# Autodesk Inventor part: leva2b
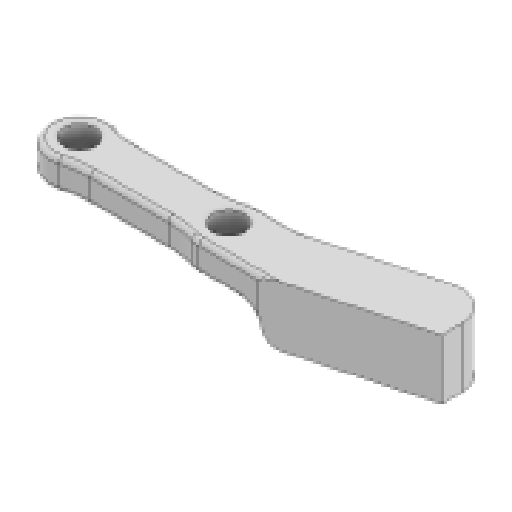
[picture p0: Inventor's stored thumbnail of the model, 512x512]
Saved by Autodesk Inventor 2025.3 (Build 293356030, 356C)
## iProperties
Created: 2026-03
Part Number: leva2b
Material: Generico
Document SubType Name: Modeling
Designer: R5800u
Density: 1 g/cm^3
Appearance: Default
Author: R5800u
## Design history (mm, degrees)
sketch "Schizzo1"
  geometry: L1 (7.5, 2.5)-(-7.5, 2.5); L2 (-7.5, 2.5)-(-7.5, -2.5); L3 (-7.5, -2.5)-(7.5, -2.5); L4 (7.5, -2.5)-(7.5, 2.5); L5 (7.5, 2.5)-(-7.5, -2.5); L6 (-7.5, 2.5)-(7.5, -2.5); C1 r 3 at (7.5, 0); C2 r 3 at (-7.5, 0); 5 further points
  constraints: 12 end point, 4 midpoint, 2 centre point, 2 parallel, 1 horizontal, 1 perpendicular
  dimensions: "d0" = 15 distance of L3.end L2.end; "d1" = 5 distance of L2.end L1.end; "d4" = 6 diameter of C1; "d5" = 6 diameter of C2
extrude "Estrusione1" new body sketch "Schizzo1" distance "d2" = 3; taper "d3" = 0 deg
sketch "Schizzo2"
  geometry: A1 r 3 centre (7.5, 0) between (5.842, -2.5) and (5.842, 2.5) reference; A2 r 3 centre (-7.5, 0) between (-5.842, 2.5) and (-5.842, -2.5) reference; 3 further points
  constraints: 2 coincident
hole "Foro1" sketch "Schizzo2" at (7.5, 0), (-7.5, 0) diameter "d6" = 3.2; stored, may be unused: countersink angle "d10" = 90 deg, drill point angle "d12" = 118 deg; dims "d7" = 6, "d8" = 6.5, "d9" = 3.4, "d11" = 8
sketch "Schizzo3"
  geometry: L1 (5.842, 2.5)-(-5.842, 2.5) reference; L2 (-5.842, -2.5)-(5.842, -2.5) reference; L3 (7.5, 0)-(7.5, 3); L4 (7.5, 0)-(7.5, -3); L5 (7.5, 3)-(13.5, 3); L6 (13.5, 3)-(13.5, -3); L7 (13.5, -3)-(7.5, -3); L8 (7.5, -3)-(7.5, 3); L9 (13.5, -3)-(10.036, 3); C1 r 1.6 at (-7.5, 0) reference; C2 r 1.6 at (7.5, 0) reference; A1 r 3 centre (7.5, 0) between (5.842, -2.5) and (5.842, 2.5) reference; A2 r 3 centre (-7.5, 0) between (-5.842, 2.5) and (-5.842, -2.5) reference; 2 further points
  constraints: 14 end point, 3 point on line, 2 parallel, 2 point on circle, 1 horizontal, 1 perpendicular, 1 vertical
  dimensions: "d13" = 6 distance of L6.end L7.end; "d16" = 30 deg angle of L9 L6
extrude "Estrusione2" join sketch "Schizzo3" stored distance "d14" = 10; taper "d15" = 0 deg
fillet "Raccordo1" dims "d17" = 10
sketch "Schizzo7"
  geometry: L1 (13.5, -3)-(13.5, 3) reference; L2 (13.5, 3)-(16.5, -2.196); L3 (16.5, -2.196)-(13.5, -3); L4 (13.5, -3)-(16.098, -1.5); 1 further point
  constraints: 6 end point, 1 perpendicular, 1 point on line
  dimensions: "d30" = 6 distance of L1.end L2.end; "d31" = 30 deg angle of L2 L1
extrude "Estrusione6" join sketch "Schizzo7" stored distance "d32" = 10; taper "d33" = 0 deg
sketch "Schizzo8"
  geometry: L1 (13.5, 3)-(13.5, -3) reference; L2 (13.5, -3)-(27.964, 0.973); L3 (27.964, 0.973)-(27.964, 6.973); L4 (27.964, 6.973)-(13.5, 3); L5 (27.964, 3.973)-(13.5, 0); 1 further point
  constraints: 8 end point, 2 midpoint, 1 parallel
  dimensions: "d34" = 6 distance of L2.end L3.end; "d35" = 74.64 deg angle of L1 L2; "d36" = 15 distance of L5.start L5.end
extrude "Estrusione7" join sketch "Schizzo8" distance "d37" = 10; taper "d38" = 0 deg
chamfer "Smusso1" distance "d39" = 2; stored, may be unused: second distance "d40" = 2, angle "d41" = 45 deg
fillet "Raccordo2" dims "d42" = 2
fillet "Raccordo3" dims "d43" = 3
fillet "Raccordo4" dims "d44" = 0.5
fillet "Raccordo5" dims "d45" = 0.5
node "Solido1"
node "Linea chiusa proiettata1"
